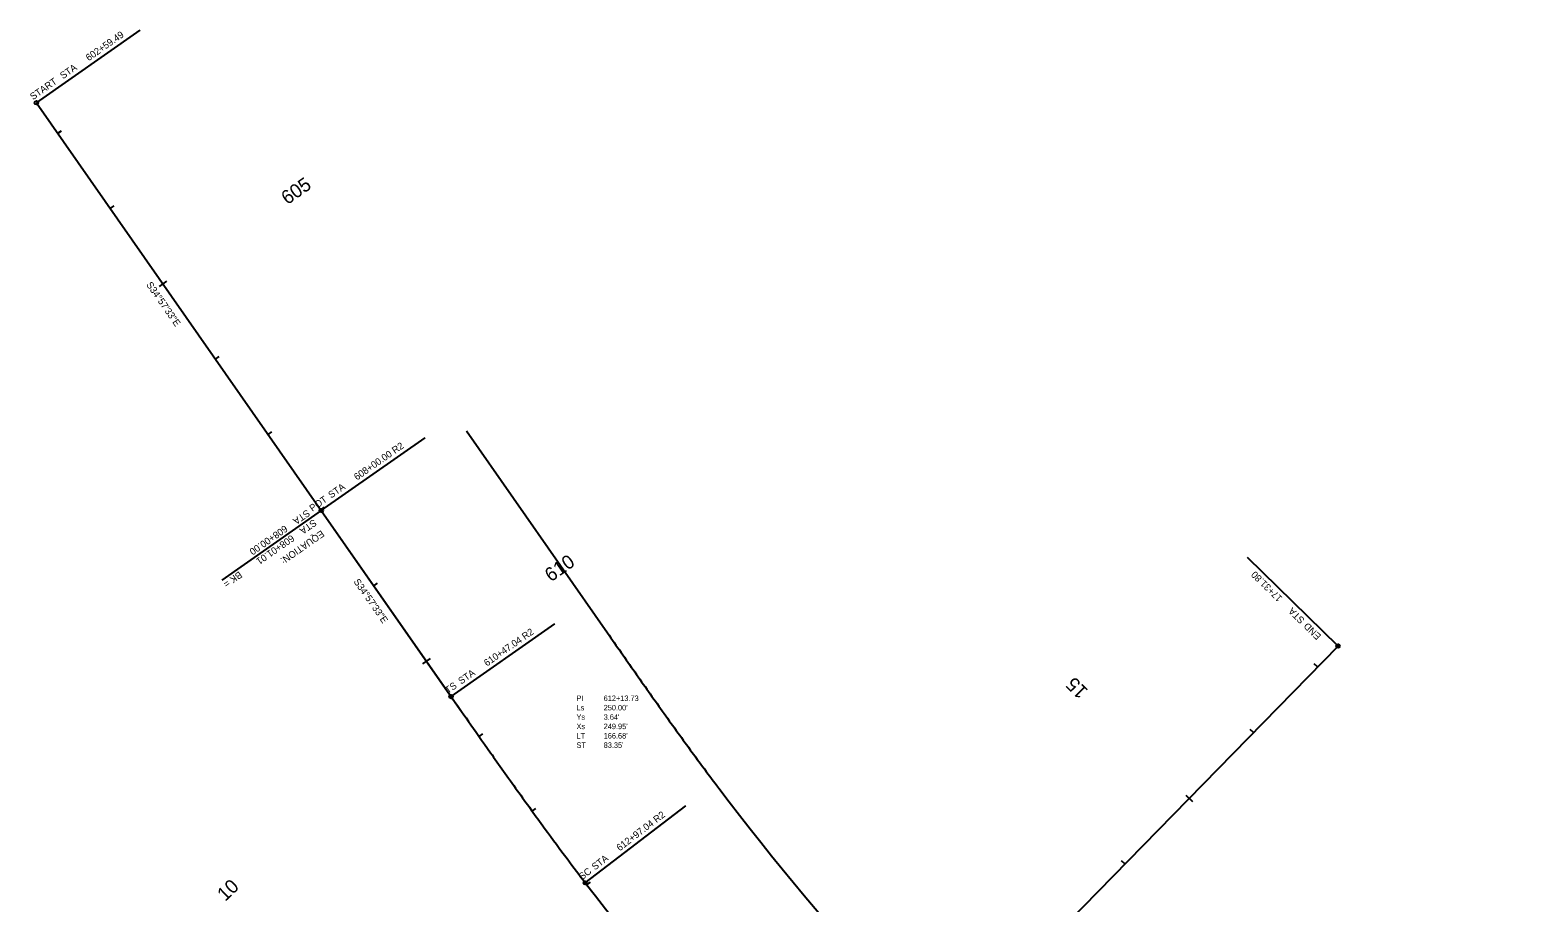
# Model space of a CAD drawing. Extents: x 1604882 to 1608571, y 865355 to 868094.
# Drawn here: x 1604886 to 1606528, y 867144 to 868094 of the extents above; entities that cross this region are included whole.
import ezdxf

# ---------------------------------------------------------------- set-up
doc = ezdxf.new("R2010")
doc.units = 0
for name, color, linetype in [('Default', 7, 'Continuous'), ('Modeling-Contours-Major-Existing', 7, 'Continuous'), ('Modeling-Contours-Minor-Existing', 7, 'Continuous'), ('Modeling-Flow Arrows-Existing', 7, 'Continuous'), ('Modeling-Island-Existing', 7, 'Continuous'), ('Modeling-Low Points-Existing', 7, 'Continuous'), ('Modeling-Spot-Existing', 7, 'Continuous'), ('Modeling-Triangle Verticies-Existing', 7, 'Continuous'), ('Modeling-Triangles-Existing', 7, 'Continuous')]:
    doc.layers.add(name, color=color, linetype=linetype)

msp = doc.modelspace()

# ---------------------------------------------------------------- linework, layer by layer
at = {"layer": 'Default'}
for p, q in [((1605360.7, 867657.5), (1605514.3, 867437.7)), ((1605360.7, 867657.5), (1605514.4, 867437.7)), ((1605202.6, 867570.8), (1605356.2, 867351)), ((1605202.6, 867570.8), (1605344.1, 867368.3)), ((1605482.8, 866578.3), (1606310.3, 867423.2))]:
    msp.add_line(p, q, dxfattribs=at)
for centre, start, end in [((1607922.2, 868994.2), 217.0392, 240.877), ((1607922.2, 868994.2), 217.0392, 240.877), ((1607764.2, 868907.8), 217.4592, 240.4569)]:
    msp.add_arc(centre, 2864.6, start, end, dxfattribs=at)
for points in [[(1605514.4, 867437.7), (1605524.3, 867423.5), (1605544.1, 867395), (1605574.1, 867352.6), (1605604.5, 867310.3), (1605625.1, 867282.5), (1605635.6, 867268.7)], [(1605514.4, 867437.7), (1605524.3, 867423.5), (1605544.1, 867395), (1605574.1, 867352.6), (1605604.5, 867310.3), (1605625.1, 867282.5), (1605635.6, 867268.7)], [(1605344.1, 867368.3), (1605350.1, 867359.8), (1605362.1, 867342.7), (1605386, 867308.6), (1605416.1, 867266), (1605446.6, 867223.9), (1605471.4, 867190.4), (1605484, 867173.8), (1605490.3, 867165.5)]]:
    msp.add_open_spline(points, degree=3, dxfattribs=at)
at = {"layer": 'Modeling-Contours-Minor-Existing'}
for p, q in [((1605034.2, 867820.3), (1605026, 867814.6)), ((1605321.3, 867409.7), (1605313.1, 867404)), ((1606144.5, 867261.1), (1606151.7, 867254.1))]:
    msp.add_line(p, q, dxfattribs=at)
at = {"layer": 'Modeling-Island-Existing'}
for p, q in [((1606311.5, 867423.2), (1606309, 867423.2)), ((1606310.3, 867424.4), (1606310.3, 867421.9))]:
    msp.add_line(p, q, dxfattribs=at)
msp.add_circle((1606310.3, 867423.2), 1.25, dxfattribs=at)
at = {"layer": 'Modeling-Spot-Existing'}
for p, q in [((1604892.3, 868014.6), (1605005.4, 868093.6)), ((1605005.4, 868093.6), (1605005.4, 868093.6)), ((1605202.6, 867570.8), (1605315.7, 867649.8)), ((1605315.7, 867649.8), (1605315.7, 867649.8)), ((1605202.6, 867570.8), (1605094.4, 867495.1)), ((1606310.3, 867423.2), (1606211.7, 867519.7)), ((1606211.7, 867519.7), (1606211.7, 867519.7)), ((1605344.1, 867368.3), (1605457.2, 867447.4)), ((1605457.2, 867447.4), (1605457.2, 867447.4)), ((1605490.3, 867165.5), (1605599.9, 867249.5)), ((1605599.9, 867249.5), (1605599.9, 867249.5))]:
    msp.add_line(p, q, dxfattribs=at)
for centre in [(1604892.3, 868014.6), (1605202.6, 867570.8), (1605202.6, 867570.8), (1606310.3, 867423.2), (1605344.1, 867368.3), (1605490.3, 867165.5)]:
    msp.add_circle(centre, 1.98, dxfattribs=at)
at = {"layer": 'Modeling-Triangle Verticies-Existing'}
for p, q in [((1604915.5, 867981.4), (1604919.6, 867984.2)), ((1604972.8, 867899.4), (1604976.9, 867902.3)), ((1605087.4, 867735.5), (1605091.5, 867738.4)), ((1605144.7, 867653.5), (1605148.8, 867656.4)), ((1605202, 867571.6), (1605206.1, 867574.5)), ((1605202.6, 867570.8), (1605206.7, 867573.6)), ((1605259.9, 867488.8), (1605264, 867491.7)), ((1606288, 867400.5), (1606284.5, 867404)), ((1605374.5, 867324.9), (1605378.6, 867327.8)), ((1606218.1, 867329), (1606214.5, 867332.5)), ((1605432.5, 867243.4), (1605436.5, 867246.3)), ((1606078.1, 867186.1), (1606074.6, 867189.6)), ((1605492.1, 867163.2), (1605496.1, 867166.2))]:
    msp.add_line(p, q, dxfattribs=at)
at = {"layer": 'Modeling-Triangles-Existing'}
for p, q in [((1604892.3, 868014.6), (1605202.6, 867570.8)), ((1605202.6, 867570.8), (1605344.1, 867368.3)), ((1605482.8, 866578.3), (1606310.3, 867423.2))]:
    msp.add_line(p, q, dxfattribs=at)
msp.add_arc((1607764.2, 868907.8), 2864.6, 217.4592, 240.4569, dxfattribs=at)
msp.add_open_spline([(1605344.1, 867368.3), (1605350.1, 867359.8), (1605362.1, 867342.7), (1605386, 867308.6), (1605416.1, 867266), (1605446.6, 867223.9), (1605471.4, 867190.4), (1605484, 867173.8), (1605490.3, 867165.5)], degree=3, dxfattribs=at)

# ---------------------------------------------------------------- texts
at = {"layer": 'Modeling-Contours-Major-Existing'}
for s, rotation, p in [('605', 34.959, (1605165.7, 867903.1)), ('610', 34.959, (1605452.8, 867492.5)), ('15', 135.5963, (1606038.9, 867375)), ('10', 43.87, (1605098, 867144.6))]:
    msp.add_text(s, height=15, rotation=rotation, dxfattribs=at).set_placement(p)
at = {"layer": 'Modeling-Flow Arrows-Existing'}
for p in [(1605011.6, 867816.5), (1605237.5, 867493.3)]:
    msp.add_text('S34°57\'33"E', height=7.5, rotation=304.959, dxfattribs=at).set_placement(p)
at = {"layer": 'Modeling-Low Points-Existing'}
for s, p in [('PI   ', (1605480.7, 867363.4)), ('Ls   ', (1605480.7, 867353.2)), ('612+13.73', (1605510.3, 867363.4)), ("250.00'", (1605510.3, 867353.2)), ('Ys   ', (1605480.7, 867343)), ("3.64'", (1605510.3, 867343)), ('Xs   ', (1605480.7, 867332.8)), ('LT   ', (1605480.7, 867322.6)), ("249.95'", (1605510.3, 867332.8)), ("166.68'", (1605510.3, 867322.6)), ('ST   ', (1605480.7, 867312.4)), ("83.35'", (1605510.3, 867312.4))]:
    msp.add_text(s, height=6, dxfattribs=at).set_placement(p)
at = {"layer": 'Modeling-Spot-Existing'}
for s, rotation, p in [('602+59.49', 34.959, (1604949.3, 868059.7)), (' STA ', 34.959, (1604919, 868038.5)), ('START', 34.959, (1604888.6, 868017.3)), ('608+00.00 R2', 34.959, (1605241.5, 867603.3)), ('POT', 34.959, (1605193, 867569.3)), (' STA ', 34.959, (1605211.2, 867582.1)), ('STA ', 214.959, (1605187, 867572.2)), ('608+00.00', 214.959, (1605162.7, 867555.2)), ('STA ', 214.959, (1605194.3, 867561.7)), ('608+01.01', 214.959, (1605170, 867544.8)), ('EQUATION:', 214.959, (1605202.6, 867549.7)), (' BK =', 214.959, (1605115.4, 867506.6)), ('17+31.80', 135.5963, (1606250.2, 867476)), (' STA ', 135.5963, (1606276.6, 867450.1)), ('610+47.04 R2', 34.959, (1605383.1, 867400.8)), ('END', 135.5963, (1606292.5, 867434.6)), (' STA ', 34.959, (1605352.8, 867379.6)), ('TS', 34.959, (1605340.6, 867371.1)), ('612+97.04 R2', 37.4592, (1605527.8, 867199.7)), (' STA ', 37.4592, (1605498.5, 867177.2)), ('SC', 37.4592, (1605486.7, 867168.2))]:
    msp.add_text(s, height=7.5, rotation=rotation, dxfattribs=at).set_placement(p)

doc.saveas('drawing.dxf')
